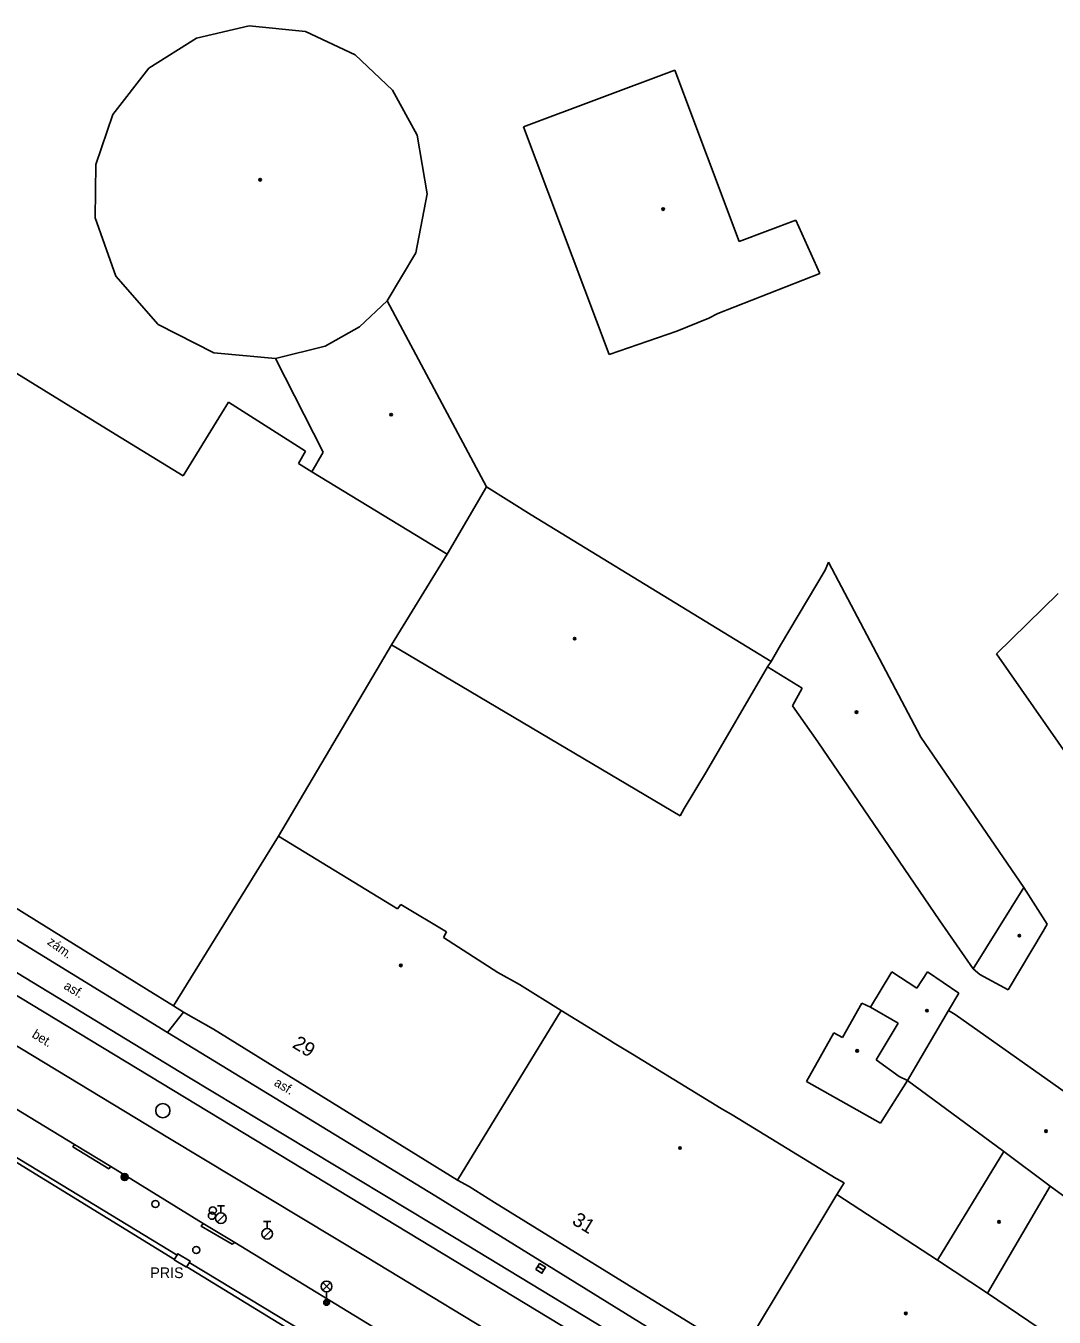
# Model space of a CAD drawing. Extents: x -598341 to -594502, y -1162301 to -1161406.
# Drawn here: x -597577.4 to -597505.2, y -1161626.1 to -1161535.4 of the extents above; entities that cross this region are included whole.
import ezdxf

# ---------------------------------------------------------------- set-up
doc = ezdxf.new("R2010")
doc.units = 0
for name, color, linetype in [('Vrstva 10', 7, 'Continuous'), ('Vrstva 11', 7, 'Continuous'), ('Vrstva 13', 7, 'Continuous'), ('Vrstva 24', 7, 'Continuous'), ('Vrstva 25', 7, 'Continuous'), ('Vrstva 27', 7, 'Continuous'), ('Vrstva 28', 7, 'Continuous'), ('Vrstva 33', 7, 'Continuous'), ('Vrstva 39', 7, 'Continuous'), ('Vrstva 40', 7, 'Continuous'), ('Vrstva 41', 7, 'Continuous'), ('Vrstva 46', 7, 'Continuous'), ('Vrstva 5', 7, 'Continuous'), ('Vrstva 7', 7, 'Continuous')]:
    doc.layers.add(name, color=color, linetype=linetype)

msp = doc.modelspace()

# ---------------------------------------------------------------- linework, layer by layer
at = {"layer": 'Vrstva 10'}
for p, q in [((-597571.46, -1161615.5), (-597564.97, -1161619.51)), ((-597548.62, -1161617.58), (-597530.95, -1161628.51)), ((-597564.97, -1161619.51), (-597562.74, -1161620.84)), ((-597562.74, -1161620.84), (-597545.98, -1161631.07))]:
    msp.add_line(p, q, dxfattribs=at)
for points in [[(-597603.13, -1161584.15), (-597598.66, -1161586.94), (-597567.48, -1161606.1)], [(-597567.48, -1161606.1), (-597548.62, -1161617.58)], [(-597580.26, -1161610.16), (-597573.99, -1161613.95)], [(-597573.99, -1161613.95), (-597571.46, -1161615.5)]]:
    msp.add_lwpolyline(points, dxfattribs=at)
at = {"layer": 'Vrstva 11'}
msp.add_line((-597567.48, -1161606.1), (-597566.34, -1161604.66), dxfattribs=at)
for points in [[(-597491.79, -1161654.07), (-597514.39, -1161640.46), (-597547.21, -1161620.56), (-597565.99, -1161609.22), (-597585.64, -1161597.29), (-597623.42, -1161574.41), (-597631.49, -1161569.4)], [(-597573.99, -1161613.95), (-597574.11, -1161614.12), (-597571.6, -1161615.66), (-597571.46, -1161615.5)], [(-597564.97, -1161619.51), (-597565.11, -1161619.69), (-597562.92, -1161620.95), (-597562.74, -1161620.84)]]:
    msp.add_lwpolyline(points, dxfattribs=at)
at = {"layer": 'Vrstva 13'}
msp.add_line((-597623.58, -1161575.96), (-597524.08, -1161636.17), dxfattribs=at)
msp.add_lwpolyline([(-597525.62, -1161638.79), (-597532.4, -1161634.67), (-597542.09, -1161628.78), (-597553.46, -1161621.89), (-597567.32, -1161613.53), (-597583.27, -1161603.88), (-597607.87, -1161588.96), (-597620.98, -1161581.06)], dxfattribs=at)
at = {"layer": 'Vrstva 24'}
msp.add_lwpolyline([(-597566.997, -1161622.057), (-597566.139, -1161622.572), (-597565.882, -1161622.143), (-597566.74, -1161621.628)], close=True, dxfattribs=at)
at = {"layer": 'Vrstva 25'}
for radius in [0.25, 0.2, 0.15, 0.1, 0.05]:
    msp.add_circle((-597570.48, -1161616.24), radius, dxfattribs=at)
at = {"layer": 'Vrstva 27'}
msp.add_line((-597541.472, -1161622.528), (-597541.048, -1161622.792), dxfattribs=at)
msp.add_lwpolyline([(-597541.604, -1161622.74), (-597541.18, -1161623.004), (-597540.916, -1161622.58), (-597541.34, -1161622.316)], close=True, dxfattribs=at)
msp.add_circle((-597567.8, -1161611.58), 0.5, dxfattribs=at)
at = {"layer": 'Vrstva 28'}
for p, q in [((-597563.97, -1161618.255), (-597563.47, -1161618.255)), ((-597563.72, -1161618.755), (-597563.72, -1161618.255)), ((-597563.978, -1161619.402), (-597563.448, -1161618.872)), ((-597560.72, -1161619.355), (-597560.22, -1161619.355)), ((-597560.47, -1161619.855), (-597560.47, -1161619.355)), ((-597560.728, -1161620.502), (-597560.198, -1161619.972))]:
    msp.add_line(p, q, dxfattribs=at)
for centre, radius in [((-597568.32, -1161618.14), 0.25), ((-597564.35, -1161618.96), 0.25), ((-597564.29, -1161618.59), 0.25), ((-597563.72, -1161619.13), 0.375), ((-597560.47, -1161620.23), 0.375), ((-597565.45, -1161621.37), 0.25)]:
    msp.add_circle(centre, radius, dxfattribs=at)
at = {"layer": 'Vrstva 33'}
for p, q in [((-597556.565, -1161624.19), (-597556.035, -1161623.66)), ((-597556.565, -1161623.66), (-597556.035, -1161624.19)), ((-597556.3, -1161624.3), (-597556.3, -1161625.05))]:
    msp.add_line(p, q, dxfattribs=at)
for centre, radius in [((-597556.3, -1161623.925), 0.375), ((-597556.3, -1161625.05), 0.2), ((-597556.3, -1161625.05), 0.145), ((-597556.3, -1161625.05), 0.0876)]:
    msp.add_circle(centre, radius, dxfattribs=at)
at = {"layer": 'Vrstva 39'}
for centre, radius in [((-597560.96, -1161546.2), 0.09), ((-597560.96, -1161546.2), 0.0398), ((-597532.66, -1161548.26), 0.09), ((-597532.66, -1161548.26), 0.0398), ((-597551.76, -1161562.7), 0.09), ((-597551.76, -1161562.7), 0.0398), ((-597538.88, -1161578.43), 0.09), ((-597538.88, -1161578.43), 0.0398), ((-597519.09, -1161583.59), 0.09), ((-597519.09, -1161583.59), 0.0398), ((-597507.65, -1161599.29), 0.09), ((-597507.65, -1161599.29), 0.0398), ((-597551.08, -1161601.38), 0.09), ((-597551.08, -1161601.38), 0.0398), ((-597514.14, -1161604.56), 0.09), ((-597514.14, -1161604.56), 0.0398), ((-597519.04, -1161607.38), 0.09), ((-597519.04, -1161607.38), 0.0398), ((-597505.78, -1161613.02), 0.09), ((-597505.78, -1161613.02), 0.0398), ((-597531.48, -1161614.2), 0.09), ((-597531.48, -1161614.2), 0.0398), ((-597509.08, -1161619.39), 0.09), ((-597509.08, -1161619.39), 0.0398), ((-597515.62, -1161625.82), 0.09), ((-597515.62, -1161625.82), 0.0398)]:
    msp.add_circle(centre, radius, dxfattribs=at)
at = {"layer": 'Vrstva 5'}
for p, q in [((-597565.44, -1161536.26), (-597561.74, -1161535.39)), ((-597561.74, -1161535.39), (-597557.79, -1161535.8)), ((-597568.79, -1161538.37), (-597565.44, -1161536.26)), ((-597557.79, -1161535.8), (-597554.3, -1161537.43)), ((-597554.3, -1161537.43), (-597551.68, -1161539.91)), ((-597571.32, -1161541.62), (-597568.79, -1161538.37)), ((-597542.46, -1161542.49), (-597531.84, -1161538.5)), ((-597531.84, -1161538.5), (-597527.32, -1161550.53)), ((-597551.68, -1161539.91), (-597549.93, -1161543.08)), ((-597572.51, -1161545.13), (-597571.32, -1161541.62)), ((-597536.46, -1161558.48), (-597542.46, -1161542.49)), ((-597549.93, -1161543.08), (-597549.23, -1161547.2)), ((-597601.97, -1161545.08), (-597571.44, -1161563.88)), ((-597572.54, -1161548.88), (-597572.51, -1161545.13)), ((-597549.23, -1161547.2), (-597550.02, -1161551.34)), ((-597571.09, -1161552.97), (-597572.54, -1161548.88)), ((-597527.32, -1161550.53), (-597523.35, -1161549.04)), ((-597521.66, -1161552.78), (-597523.35, -1161549.04)), ((-597550.02, -1161551.34), (-597552.04, -1161554.71)), ((-597568.12, -1161556.36), (-597571.09, -1161552.97)), ((-597521.66, -1161552.78), (-597528.82, -1161555.59)), ((-597553.99, -1161556.52), (-597552.04, -1161554.71)), ((-597545.08, -1161567.77), (-597552.04, -1161554.71)), ((-597529.46, -1161555.93), (-597531.7, -1161556.83)), ((-597528.82, -1161555.59), (-597529.46, -1161555.93)), ((-597564.21, -1161558.35), (-597568.12, -1161556.36)), ((-597556.41, -1161557.9), (-597553.99, -1161556.52)), ((-597531.7, -1161556.83), (-597536.46, -1161558.48)), ((-597559.88, -1161558.76), (-597556.41, -1161557.9)), ((-597559.88, -1161558.76), (-597564.21, -1161558.35)), ((-597556.55, -1161565.33), (-597559.88, -1161558.76)), ((-597563.67, -1161562.62), (-597563.18, -1161561.83)), ((-597563.18, -1161561.83), (-597557.79, -1161565.26)), ((-597566.38, -1161567), (-597563.67, -1161562.62)), ((-597571.44, -1161563.88), (-597566.38, -1161567)), ((-597557.79, -1161565.26), (-597558.28, -1161566.12)), ((-597558.28, -1161566.12), (-597557.34, -1161566.71)), ((-597557.34, -1161566.71), (-597556.55, -1161565.33)), ((-597557.34, -1161566.71), (-597547.84, -1161572.5)), ((-597547.84, -1161572.5), (-597545.08, -1161567.77)), ((-597541.94, -1161569.74), (-597545.08, -1161567.77)), ((-597541.94, -1161569.74), (-597525.09, -1161580.04)), ((-597547.84, -1161572.5), (-597551.74, -1161578.86)), ((-597521.29, -1161573.63), (-597521.05, -1161573.06)), ((-597521.05, -1161573.06), (-597520.59, -1161573.96)), ((-597524.43, -1161578.89), (-597521.29, -1161573.63)), ((-597520.59, -1161573.96), (-597514.58, -1161585.36)), ((-597504.92, -1161575.27), (-597509.26, -1161579.49)), ((-597551.74, -1161578.86), (-597552.52, -1161580.17)), ((-597531.48, -1161590.87), (-597551.74, -1161578.86)), ((-597525.09, -1161580.04), (-597524.43, -1161578.89)), ((-597504.06, -1161586.95), (-597509.26, -1161579.49)), ((-597552.52, -1161580.17), (-597559.67, -1161592.3)), ((-597529.63, -1161587.75), (-597525.33, -1161580.41)), ((-597525.33, -1161580.41), (-597525.09, -1161580.04)), ((-597525.33, -1161580.41), (-597522.89, -1161581.91)), ((-597522.89, -1161581.91), (-597523.57, -1161583.14)), ((-597523.57, -1161583.14), (-597521.8, -1161585.68)), ((-597513.23, -1161598.24), (-597521.8, -1161585.68)), ((-597514.58, -1161585.36), (-597507.34, -1161595.91)), ((-597529.63, -1161587.75), (-597531.18, -1161590.37)), ((-597531.18, -1161590.37), (-597531.48, -1161590.87)), ((-597567.05, -1161604.23), (-597559.67, -1161592.3)), ((-597559.67, -1161592.3), (-597551.32, -1161597.4)), ((-597574.74, -1161599.44), (-597582.22, -1161594.82)), ((-597510.89, -1161601.62), (-597507.34, -1161595.91)), ((-597507.34, -1161595.91), (-597505.69, -1161598.49)), ((-597551.32, -1161597.4), (-597551.09, -1161597.1)), ((-597551.09, -1161597.1), (-597547.88, -1161599.01)), ((-597510.89, -1161601.62), (-597513.23, -1161598.24)), ((-597505.69, -1161598.49), (-597505.98, -1161598.97)), ((-597568.94, -1161603.04), (-597574.74, -1161599.44)), ((-597547.88, -1161599.01), (-597548.1, -1161599.43)), ((-597548.1, -1161599.43), (-597544.28, -1161601.87)), ((-597505.98, -1161598.97), (-597508.44, -1161603.1)), ((-597544.28, -1161601.87), (-597542.76, -1161602.72)), ((-597518.11, -1161604.32), (-597516.61, -1161601.82)), ((-597516.61, -1161601.82), (-597514.84, -1161602.98)), ((-597514.84, -1161602.98), (-597514.09, -1161601.84)), ((-597514.09, -1161601.84), (-597511.9, -1161603.32)), ((-597510.42, -1161602.02), (-597510.89, -1161601.62)), ((-597508.44, -1161603.1), (-597510.42, -1161602.02)), ((-597567.05, -1161604.23), (-597568.94, -1161603.04)), ((-597542.76, -1161602.72), (-597539.83, -1161604.54)), ((-597511.9, -1161603.32), (-597512.63, -1161604.54)), ((-597566.34, -1161604.66), (-597567.05, -1161604.23)), ((-597518.71, -1161604.04), (-597520.07, -1161606.45)), ((-597518.11, -1161604.32), (-597518.71, -1161604.04)), ((-597516.16, -1161605.43), (-597518.11, -1161604.32)), ((-597564.23, -1161605.86), (-597566.34, -1161604.66)), ((-597539.83, -1161604.54), (-597547.1, -1161616.46)), ((-597539.83, -1161604.54), (-597536.44, -1161606.62)), ((-597512.63, -1161604.54), (-597515.5, -1161609.46)), ((-597512.63, -1161604.54), (-597512.15, -1161604.83)), ((-597512.15, -1161604.83), (-597496.37, -1161616)), ((-597559.94, -1161608.52), (-597564.23, -1161605.86)), ((-597520.67, -1161606.11), (-597522.6, -1161609.53)), ((-597520.07, -1161606.45), (-597520.67, -1161606.11)), ((-597517.71, -1161608.01), (-597516.16, -1161605.43)), ((-597536.44, -1161606.62), (-597536.1, -1161606.83)), ((-597536.1, -1161606.83), (-597535.16, -1161607.4)), ((-597535.16, -1161607.4), (-597534.82, -1161607.61)), ((-597534.82, -1161607.61), (-597528.6, -1161611.42)), ((-597547.1, -1161616.46), (-597559.94, -1161608.52)), ((-597516.1, -1161609.18), (-597517.71, -1161608.01)), ((-597522.6, -1161609.53), (-597517.41, -1161612.47)), ((-597517.41, -1161612.47), (-597515.5, -1161609.46)), ((-597515.5, -1161609.46), (-597516.1, -1161609.18)), ((-597508.74, -1161614.46), (-597515.5, -1161609.46)), ((-597528.6, -1161611.42), (-597527.81, -1161611.88)), ((-597527.81, -1161611.88), (-597520.52, -1161616.35)), ((-597513.4, -1161622.09), (-597508.74, -1161614.46)), ((-597508.74, -1161614.46), (-597505.49, -1161616.89)), ((-597546.28, -1161616.91), (-597547.1, -1161616.46)), ((-597544.5, -1161618.04), (-597546.28, -1161616.91)), ((-597520.52, -1161616.35), (-597519.96, -1161616.66)), ((-597519.96, -1161616.66), (-597520.46, -1161617.48)), ((-597505.49, -1161616.89), (-597509.89, -1161624.4)), ((-597500.42, -1161620.57), (-597505.49, -1161616.89)), ((-597520.46, -1161617.48), (-597527.19, -1161628.66)), ((-597520.46, -1161617.48), (-597513.4, -1161622.09)), ((-597534.12, -1161624.44), (-597544.5, -1161618.04)), ((-597513.4, -1161622.09), (-597509.89, -1161624.4)), ((-597529.88, -1161627.05), (-597534.12, -1161624.44)), ((-597509.89, -1161624.4), (-597506.25, -1161626.85))]:
    msp.add_line(p, q, dxfattribs=at)
at = {"layer": 'Vrstva 7'}
for points in [[(-597583.04, -1161612.38), (-597583.14, -1161612.66), (-597580.75, -1161613.59), (-597566.98, -1161622.03)], [(-597583.04, -1161612.38), (-597580.67, -1161613.31), (-597566.79, -1161621.72)], [(-597565.94, -1161622.24), (-597554.53, -1161629.15)], [(-597566.12, -1161622.55), (-597554.77, -1161629.51)]]:
    msp.add_lwpolyline(points, dxfattribs=at)

# ---------------------------------------------------------------- texts
at = {"layer": 'Vrstva 40'}
for s, rotation, p in [('zám.', 324.44731, (-597575.97, -1161599.85)), ('asf.', 328.67408, (-597574.81, -1161602.98)), ('bet.', 328.45618, (-597577.04, -1161606.39)), ('asf.', 329.03147, (-597560.04, -1161609.78))]:
    msp.add_text(s, height=0.65, rotation=rotation, dxfattribs=at).set_placement(p)
at = {"layer": 'Vrstva 41'}
msp.add_text('PRIS', height=0.75, dxfattribs=at).set_placement((-597568.68, -1161623.34))
at = {"layer": 'Vrstva 46'}
for s, rotation, p in [('29', 328.43, (-597558.77, -1161607.1)), ('31', 328.56, (-597539.13, -1161619.5))]:
    msp.add_text(s, height=1, rotation=rotation, dxfattribs=at).set_placement(p)

doc.saveas('drawing.dxf')
